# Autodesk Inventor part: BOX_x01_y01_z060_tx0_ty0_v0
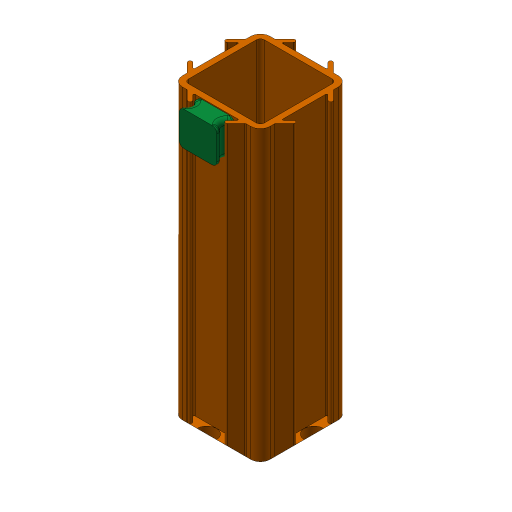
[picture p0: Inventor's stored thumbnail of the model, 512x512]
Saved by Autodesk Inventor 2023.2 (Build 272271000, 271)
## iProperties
RuleStatus: InUse
Created: 2024-02
Part Number: BOX_x01_y01_z060_tx0_ty0_v0
Material: -
Document SubType Name: Modellieren
Designer: ott
Mass: 0.00617105 g
Surface Area: 105.579 cm^2
Volume: 6.17105 cm^3
Density: 0.001 g/cm^3
Sheet Metal Rule: Standard
Appearance: -
BeforeDocSave0: file://Stammdaten_MODELL_Eigenschaften
BP_Dateityp: Einzelteil
BP_Farbe: -
BP_Masse: 0,000
BP_Material: -
BP_maxX: 0.0
BP_maxY: 0.0
BP_maxZ: 0.0
BP_Mengeneinheit: St.
Author: ott
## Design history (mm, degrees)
sketch "Skizze1"
  geometry: L1 (-21.6, 0)-(129.6, 0) reference; L2 (0, -8.4)-(0, 50.4) reference; L3 (2, 2)-(20, 2); L4 (20, 2)-(20, 20); L5 (20, 20)-(2, 20); L6 (2, 20)-(2, 2); L7 (3.2, 3.2)-(18.8, 3.2); L8 (18.8, 3.2)-(18.8, 18.8); L9 (18.8, 18.8)-(3.2, 18.8); L10 (3.2, 18.8)-(3.2, 3.2); L11 (0, 0)-(22, 0); L12 (22, 0)-(22, 22); L13 (22, 22)-(0, 22); L14 (0, 22)-(0, 0); L15 (22, 11)-(0, 11); L16 (11, 0)-(11, 22); L17 (2, 17)-(0, 15); L18 (0, 15)-(0, 7); L19 (2, 5)-(0, 7); L20 (2, 5)-(2, 17); L21 (7, 0)-(15, 0); L22 (15, 0)-(17, 2); L23 (17, 2)-(5, 2); L24 (5, 2)-(7, 0); L25 (2, 15.869)-(0, 13.869); L26 (0, 8.131)-(2, 6.131); L27 (6.131, 2)-(8.131, 0); L28 (15.869, 2)-(13.869, 0); 5 further points
  constraints: 52 end point, 16 point on line, 7 midpoint, 7 parallel, 7 perpendicular, 2 horizontal, 3 other
  dimensions: "d45" = 1.2 distance between parallel lines of L6 L10 (derived); "d46" = 2 distance between parallel lines of L3 L1 (= ü); "d47" = 2 distance between parallel lines of L2 L6 (= ü); "d48" = 22 distance of L12.end L13.end (= px); "d49" = 22 distance of L11.end L12.end (derived); "d50" = 18 distance between parallel lines of L6 L4 (computed from px, nx, ü); "d51" = 18 distance of L5.end L3.start (computed from py, ny, ü); "d53" = 90 deg angle of L17 L19; "d54" = 8 distance of L18.end L17.end (= bw); "d55" = 90 deg angle of L22 L24; "d56" = 8 distance of L21.start L21.end (= bw); "d57" = 0.8 distance between parallel lines of L19 L26 (= tw); "d58" = 0.8 distance from line of L25 L17.end (= tw); "d59" = 0.8 distance between parallel lines of L22 L28 (= tw); "d60" = 0.8 distance from line of point (6, 1) L27 (= tw)
extrude "Extrusion6" new body sketch "Skizze1" distance "d61" = 61.2 (derived); taper "d62" = 0 deg
chamfer "Fase2" distance "d63" = 2; stored, may be unused: second distance "d64" = 2, angle "d65" = 45 deg
fillet "Rundung6" dims "d66" = 2, "d67" = 3
feature "Wandung2" dims "d68" = 1.2 (derived)
extrude "Extrusion7" join sketch "Skizze1" stored distance "d69" = 11 (computed from nz, pz); taper "d70" = 0 deg
extrude "Extrusion8" cut sketch "Skizze1" stored distance "d71" = 10; taper "d72" = 0 deg
fillet "Rundung7" dims "d73" = 0.4 (= 0.5 x tw), "d85" = 0.2 (derived)
extrude "Extrusion9" join sketch "Skizze1" stored distance "d74" = 10; taper "d75" = 0 deg
extrude "Extrusion10" cut sketch "Skizze1" stored distance "d76" = 10; taper "d77" = 0 deg
fillet "Rundung8" dims "d78" = 0.4 (derived), "d86" = 0.2 (derived)
sketch "Skizze5"
  geometry: L1 (0.551, -2)-(8.22, -2) reference; L2 (0, 0)-(8.772, 0) reference; C1 r 2 at (4.386, -2); 1 further point
  constraints: 1 centre point, 1 midpoint, 1 tangent
extrude "Extrusion12" cut sketch "Skizze5" extent not by distance; stored distance "d102" = 0; taper "d103" = 0 deg
sketch "Skizze6"
  geometry: L1 (0, 8.772)-(0, 0) reference; L2 (-1.317, 7.937)-(-0.341, 8.913) reference; L3 (-2, 8.22)-(-2, 0.551) reference; L4 (-0.341, -0.141)-(-1.317, 0.834) reference; L5 (0, 8.772)-(0, 0) reference; C1 r 2 at (-2, 4.386); A1 r 0.2 centre (-0.2, 0) between (-0.341, -0.141) and (0, 0) reference; A2 r 0.2 centre (-0.2, 8.772) between (0, 8.772) and (-0.341, 8.913) reference; A3 r 0.4 centre (-1.6, 8.22) between (-2, 8.22) and (-1.317, 7.937) reference; A4 r 0.4 centre (-1.6, 0.551) between (-1.317, 0.834) and (-2, 0.551) reference; 1 further point
  constraints: 1 centre point, 1 midpoint, 1 tangent
extrude "Extrusion13" cut sketch "Skizze6" extent not by distance; stored distance "d104" = 0; taper "d105" = 0 deg
pattern_linear "Rechteckige Anordnung4" dims "d81" = 22 (derived)
pattern_linear "Rechteckige Anordnung5" dims "d84" = 22 (derived)
node "Mitte in X"
node "Mitte in Y"
mirror "Spiegeln5"
mirror "Spiegeln6"
sketch "Skizze4"
  geometry: L1 (13, 0)-(14.834, 0) reference; L2 (6.614, 2)-(11, 2) reference; L3 (11, 1.8)-(7.58, 1.8); L4 (7.297, 1.117)-(7.566, 0.849); L5 (7.917, 0)-(11, 0); L6 (11, 0)-(11, 1.8); L7 (7.297, 1.117)-(7.114, 1.3); L8 (7.114, 1.3)-(7.114, 1.8); L9 (7.114, 1.8)-(7.58, 1.8); L10 (7.449, 0.683)-(6.473, 1.659) reference; L11 (15.527, 1.659)-(14.551, 0.683) reference; L12 (11, 2)-(15.386, 2) reference; L13 (7.166, 0)-(9, 0) reference; A1 r 0.2 centre (6.614, 1.8) between (6.614, 2) and (6.473, 1.659) reference; A2 r 0.4 centre (7.166, 0.4) between (7.166, 0) and (7.449, 0.683) reference; A3 r 0.4 centre (14.834, 0.4) between (14.551, 0.683) and (14.834, 0) reference; A4 r 0.2 centre (15.386, 1.8) between (15.527, 1.659) and (15.386, 2) reference; A5 r 0.4 centre (7.58, 1.4) between (7.58, 1.8) and (7.297, 1.117); A6 r 1.2 centre (6.717, 0) between (7.917, 0) and (7.566, 0.849); A7 r 2 centre (11, 0) between (13, 0) and (11, 2) reference; A8 r 2 centre (11, 0) between (11, 2) and (9, 0) reference; 1 further point
  constraints: 14 end point, 4 point on circle, 3 point on line, 3 tangent, 2 centre point, 2 collinear, 1 coincident, 1 horizontal, 1 perpendicular, 1 vertical
  dimensions: "d87" = 0.2 distance between parallel lines of L2 L3; "d89" = 0.4 radius of A5; "d92" = 1.2 radius of A6; "d96" = 0.5 distance of L7.end L8.end; "d98" = 0.2 distance between parallel lines of L4 L10 (derived)
extrude "Extrusion11" new body sketch "Skizze4" distance "d93" = 7 (derived); taper "d94" = 0 deg
mirror "Spiegeln7"
mirror "Spiegeln8"
fillet "Rundung9" dims "d97" = 1
node "Stegmitte in X"
node "Stegmittein Y"
sketch "Skizze10"
  geometry: L1 (0, 6)-(0, -36) reference; L2 (-8.16, 0)-(48.96, 0) reference; L3 (11, -73.44)-(11, 12.24) reference; L4 (11, 0)-(3.2, 0); L5 (3.2, -59)-(4.2, -60); L6 (4.2, -60)-(11, -60); L7 (11, -60)-(11, 0); L8 (3.2, -59)-(3.2, 0); L9 (11, 0)-(18.8, 0); L10 (18.8, 0)-(18.8, -59); L11 (18.8, -59)-(17.8, -60); L12 (17.8, -60)-(11, -60); 1 further point
  constraints: 18 end point, 5 point on line, 3 equal length, 2 perpendicular, 1 collinear, 1 horizontal, 1 vertical
  dimensions: "d133" = 60 distance between parallel lines of L2 L6 (derived); "d134" = 7.8 distance between parallel lines of L8 L3 (derived); "d135" = 45 deg angle of L8 L5; "d136" = 1 distance from line of L8 L5.end
extrude "Extrusion16" join sketch "Skizze10" stored distance "d137" = 0.8 (derived); taper "d138" = 0 deg; dims "d150" = 10, "tx" = 0 [user parameter]
pattern_linear "Rechteckige Anordnung7" dims "d139" = 0 (derived), "d141" = 22 (derived)
sketch "Skizze11"
  geometry: L1 (-11, -73.44)-(-11, 12.24) reference; L2 (0, -36)-(0, 6) reference; L3 (-128.16, 0)-(21.36, 0) reference; L4 (-11, 0)-(-3.2, 0); L5 (-3.2, 0)-(-3.2, -59); L6 (-3.2, -59)-(-4.2, -60); L7 (-4.2, -60)-(-11, -60); L8 (-11, -60)-(-17.8, -60); L9 (-17.8, -60)-(-18.8, -59); L10 (-18.8, -59)-(-18.8, 0); L11 (-18.8, 0)-(-11, 0); 1 further point
  constraints: 16 end point, 6 point on line, 3 equal length, 3 perpendicular, 1 collinear, 1 vertical
  dimensions: "d142" = 7.8 distance between parallel lines of L1 L5 (derived); "d143" = 60 distance between parallel lines of L3 L7 (derived); "d144" = 1 horizontal distance of L5.end L6.end
extrude "Extrusion17" join sketch "Skizze11" stored distance "d145" = 0.8 (derived); taper "d146" = 0 deg; dims "d151" = 10, "ty" = 0 [user parameter]
pattern_linear "Rechteckige Anordnung8" dims "d147" = 0 (derived), "d149" = 22 (derived)
sketch "Skizze12"
  geometry: L1 (0, 14.8)-(0, -0.8); L2 (0, -0.8)-(59, -0.8); L3 (59, -0.8)-(60, 0.2); L4 (60, 0.2)-(60, 13.8); L5 (60, 13.8)-(59, 14.8); L6 (59, 14.8)-(0, 14.8); L7 (-12.24, -4)-(73.44, -4) reference; L8 (0, -12.16)-(0, 44.96) reference; L9 (73.44, 7)-(-12.24, 7) reference; 3 further points
  constraints: 12 end point, 2 midpoint, 2 perpendicular, 2 point on line, 1 collinear, 1 horizontal, 1 parallel, 1 vertical
  dimensions: "d152" = 45 deg angle of L3 L4; "d153" = 1 horizontal distance of L2.end L3.end; "d154" = 60 distance between parallel lines of L4 L1 (derived); "d155" = 15.6 distance between parallel lines of L2 L6 (derived)
extrude "Extrusion18" join sketch "Skizze12" stored distance "d156" = 0.8 (derived); taper "d157" = 0 deg; dims "d158" = 20, "tx" = 0 [user parameter]
sketch "Skizze13"
  geometry: L1 (-4, 12.24)-(-4, -73.44) reference; L2 (-25.36, 0)-(124.16, 0) reference; L3 (7, 12.24)-(7, -73.44) reference; L4 (-0.8, 0)-(14.8, 0); L5 (14.8, 0)-(14.8, -59); L6 (14.8, -59)-(13.8, -60); L7 (13.8, -60)-(0.2, -60); L8 (0.2, -60)-(-0.8, -59); L9 (-0.8, -59)-(-0.8, 0); 3 further points
  constraints: 12 end point, 2 midpoint, 2 parallel, 2 perpendicular, 2 point on line, 1 collinear, 1 horizontal
  dimensions: "d159" = 45 deg angle of L7 L6; "d160" = 1 horizontal distance of L5.end L6.end; "d161" = 15.6 distance of L4.start L4.end (derived); "d162" = 60 distance between parallel lines of L7 L4 (derived)
extrude "Extrusion19" join sketch "Skizze13" stored distance "d163" = 0.8 (derived); taper "d164" = 0 deg; dims "d165" = 20, "ty" = 0 [user parameter]
chamfer "Fase4" distance "d166" = 60 (derived); stored, may be unused: second distance "d167" = 2, angle "d168" = 30 deg; dims "d178" = 10, "v" = 0 [user parameter]
chamfer "Fase5" distance "d169" = 60 (derived); stored, may be unused: second distance "d170" = 2, angle "d171" = 30 deg; dims "d179" = 10, "v" = 0 [user parameter]
chamfer "Fase6" distance "d172" = 60 (derived); stored, may be unused: second distance "d173" = 2, angle "d174" = 30 deg; dims "d180" = 10, "v" = 0 [user parameter]
chamfer "Fase7" distance "d175" = 60 (derived); stored, may be unused: second distance "d176" = 2, angle "d177" = 30 deg; dims "d181" = 10, "v" = 0 [user parameter]
node "Volumenkörper2"
node "Projizierte Kontur2"
node "Volumenkörper3"
node "Projizierte Kontur3"
other parameters: "Stärke" = 1.2 (derived), "KFaktor" = 4.4, "Biegeradius" = 1.2 (= Stärke), "BreiteBiegungsfreistellung" = 1.2 (= Stärke), "TiefeBiegungsfreistellung" = 0.6 (= 0.5 x Stärke), "GrößeEckenfreistellung" = 4.8 (= 4 x Stärke), "AbstandVerbindung" = 0.01, "MinimalRest" = 2.4 (= 2 x Stärke), "Übergangsradius" = 1.2 (= Biegeradius), "JacobiRadiusGröße" = 1.2 (= Biegeradius), "Abstandsgröße" = 1.2 (= Stärke), "px" = 22 [user parameter; used in 2 equation terms], "ü" = 2 [user parameter; used in 4 equation terms], "tw" = 0.8 [user parameter; used in 5 equation terms], "py" = 22 [user parameter; used in 1 equation term], "pz" = 22 [user parameter; used in 1 equation term], "bw" = 8 [user parameter; used in 2 equation terms], "nz" = 5 [user parameter; used in 1 equation term], "w" = 1.2 [user parameter], "d110" = 22 (derived), "d132" = 22 (derived)
